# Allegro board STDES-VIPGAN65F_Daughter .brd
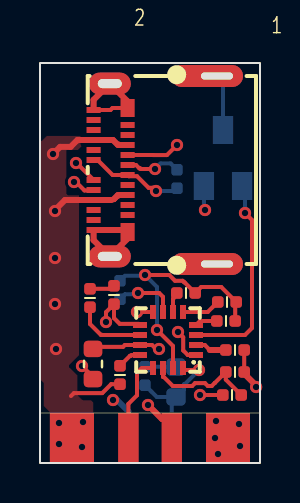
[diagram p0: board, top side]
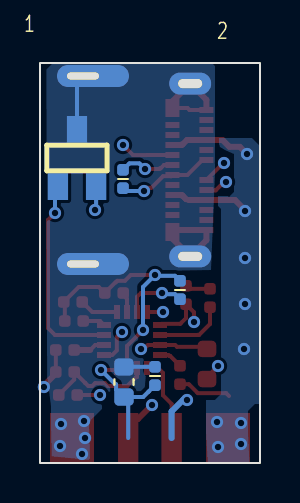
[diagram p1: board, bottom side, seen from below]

Outline 11 x 20 mm; copper layers: TOP, LAYER_1, LAYER_2, BOTTOM. Coordinates in mm from the lower left corner of the outline.
Outline path: rectangle 0,0 11,20

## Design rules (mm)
constraint set DEFAULT: 
nets with their own width: nets 2V7 GND_SIGNAL N12284642 N12284658 N12286218 N12286232 N12312816 N12312820 N12313623 N12313630 N12314144 N12315159 N12316115 N12337768 N16800338

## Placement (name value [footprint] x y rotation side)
C3  100nF  [C_0402]  5.25 4.35 90 bottom
C4  470nF  [C_0603]  6.8 4.05 90 bottom
C5  1uF  [C_0402]  4 8.65 270 bottom
C6  1uF  [C_0402]  9.75 4.55 0 top
C7  33nF  [R_0402]  3.7 8.4 270 top
D2  ESDA25L  [SOT23ST]  9.15 15.25 180 bottom
J2  USB-C-Receptacle_3  [USBCSMTMOLEX_NEW]  10.8 14.65 90 top
J5  CONN PCB 3  [PD_SBOARD]  0 2.5 0 top
NOREF  -  []  0 2.5 0 top
R5  510R  [R_0402]  4 4.4 90 top
R6  100R  [R_0402]  6.85 14.2 270 bottom
R7  0R  [R_0402]  9.75 5.65 180 top
R8  4K7  [R_0402]  9.6 3.4 180 top
R9  10K  [R_0402]  9.3 7.1 0 top
R10  4K7  [R_0402]  9.35 8.05 180 top
R11  4K7  [R_0402]  7.3 8.5 180 top
R12  3K  [R_0402]  2.5 8.25 270 top
RT1  NTC 100K  [R_0603]  2.65 4.95 270 top
U1  STUSB4761  [QFN16]  6.4 6.15 90 top

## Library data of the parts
C3-C7 = CAP NP
D2 = DIODE_DUAL_CA_JKK_2
J2 = USB-C-Receptacle_6
J5 = CONN PCB 3_1
R5-R12 = RESISTOR
RT1 = NTC
U1 = STUSB4761_0

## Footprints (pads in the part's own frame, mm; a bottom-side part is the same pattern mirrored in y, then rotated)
C_0402
  rrect 0.58x0.58 smd: 1(-0.46,0) 2(0.46,0)
C_0603
  rrect 0.87x0.97 smd: 1(-0.75,0) 2(0.75,0)
PD_SBOARD
  rect 2.2x2.5 smd: 1(1.6,-1.25) 2(1.6,-1.25) 3(9.4,-1.25) 4(9.4,-1.25)
  rect 1x2.5 smd: 5(4.42,-1.25) 6(4.42,-1.25) 7(6.59,-1.25) 8(6.59,-1.25)
QFN16
  rect 0.3x0.699 smd: 1(-0.75,-1.4) 2(-0.25,-1.4) 3(0.25,-1.4) 4(0.75,-1.4) 9(0.75,1.4) 10(0.25,1.4) 11(-0.25,1.4) 12(-0.75,1.4)
  rect 0.699x0.3 smd: 5(1.4,-0.75) 6(1.4,-0.25) 7(1.4,0.25) 8(1.4,0.75) 13(-1.4,0.75) 14(-1.4,0.25) 15(-1.4,-0.25) 16(-1.4,-0.75)
R_0402
  rrect 0.58x0.58 smd: 1(-0.46,0) 2(0.46,0)
R_0603
  rrect 0.82x0.93 smd: 1(-0.755,0) 2(0.755,0)
SOT23ST
  rect 1.016x1.4 smd: 1(-0.955,-1.4) 2(0.955,-1.4) 3(0,1.4)
USBCSMTMOLEX_NEW
  oval 1.1x2.1 hole 0.45x1.2: 25(-4.32,7.31) 26(4.32,7.31)
  oval 1.1x3.6 hole 0.35x1.6: 27(-4.7,1.95) 28(4.7,1.95)
  rect 0.3x0.699 smd: A1(-3,8.12) A2(-2.5,8.12) A3(-2,8.12) A4(-1.5,8.12) A5(-1,8.12) A6(-0.5,8.12) A7(0.5,8.12) A8(1,8.12) A9(1.5,8.12) A10(2,8.12) A11(2.5,8.12) A12(3,8.12) B2(2.25,6.42) B3(1.75,6.42) B4(1.25,6.42) B5(0.75,6.42) B6(0.25,6.42) B7(-0.25,6.42) B8(-0.75,6.42) B9(-1.25,6.42) B10(-1.75,6.42) B11(-2.25,6.42)
  rect 0.9x0.699 smd: B1(3.1,6.42) B12(-3.1,6.42)

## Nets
2V7: C5.1 R9.2 R10.1 R11.1 U1.15
GND_SIGNAL: C3.2 C4.2 C5.2 C6.2 D2.3 J2.25 J2.26 J2.27 J2.28 J2.A1 J2.A12 J2.B1 J2.B12 J5.3 J5.4 R7.1 RT1.2 U1.7
VDD: C3.1 C4.1 J5.8 U1.16
DRIVE: J5.5 U1.13
FB: C7.2 J5.6 U1.9
VOUT: J2.A4 J2.A9 J2.B4 J2.B9(VBUSB2) J5.1 J5.2 R5.1
N12284642: J2.A6 J2.B6 R6.1
N12284658: J2.A7 J2.B7 R6.2
N12286218: D2.1 J2.B5 U1.3
N12286232: D2.2 J2.A5 U1.1
N12312816: R12.2 U1.10
N12312820: C7.1 R12.1
N12313623: R11.2 U1.6
N12313630: R10.2 U1.5
N12314144: R8.2 RT1.1 U1.11
N12315159: C6.1 R8.1 U1.14
N12316115: R9.1 U1.4
N12337768: R5.2 U1.12(VSENSE)
N16800338: R7.2 U1.2
N16810216: J5.7 U1.8

Pads without a net: J2 A2 A3 A8 A10 A11 B2 B3 B8 B10 B11

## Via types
v1: diameter 0.61, hole 0.33, TOP to BOTTOM, 34 vias

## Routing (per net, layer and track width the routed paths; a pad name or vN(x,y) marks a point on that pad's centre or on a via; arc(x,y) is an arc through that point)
2V7: length 12.9
  TOP w0.2: v1(5.85,6.65) 6.65,5.85 U1.15 ; v1(5.25,9.4) 6.46,9.4 6.75,9.11 7.13,9.11 7.21,9.03 7.23,9.03 R11.1 8.06,8.8 9.06,8.8 R10.1 9.76,8 R9.2
  BOTTOM w0.2: v1(5.85,6.65) 5.85,8.8 v1(5.25,9.4) 5.21,9.36 4.25,9.36 C5.1
GND_SIGNAL: length 21.2
  TOP w0.2: J2.A12 3.52,17.65 3.62,17.75 J2.B1 ; U1.7 6.15,8.31 5.96,8.5 v1(4.9,8.5) ; 2.65,4.2 2.65,4.3 v1(2.1,4.85) ; R7.1 C6.2
  TOP w0.3: v1(10.8,3.8) 10.8,3.87 10.21,4.47 C6.2 ; J2.A12 2.68,18.16 J2.26 4.38,18.08 J2.B1 ; J2.A1 2.68,11.14 J2.25 4.38,11.22 J2.B12 4.28,11.65 J2.A1
  LAYER_1 w0.2: v1(2.1,4.85) 2.55,4.85 2.8,5.1
  BOTTOM w0.2: J2.28 9.15,19.05 D2.3 ; C5.2 4.25,8.44 4.84,8.44 v1(4.9,8.5) ; C4.2 6.79,4.81 C3.2
  vias: v1(8.8,2.1) v1(8.75,1.25) v1(8.9,0.45) v1(9.95,1.95) v1(10,0.85)
VDD: length 6.7
  TOP w0.2: v1(7.95,4.65) 7.25,4.65 U1.16
  BOTTOM w0.2: 7.2,3.9 v1(7.95,4.65) ; 7.2,3.9 7.2,3.65 6.85,3.3 C4.1 ; 7.2,3.9 7.2,3.95 ; C4.1 6.59,3.09 J5.8 ; C4.1 5.84,3.3 5.57,3.57 C3.1
DRIVE: length 4.3
  TOP w0.2: U1.13 5.09,4.75 4.85,4.51 4.85,3.39 4.42,2.96 J5.5
FB: length 9.6
  TOP w0.2: U1.9 4.95,6.96 3.99,6.96 3.7,7.24 C7.2 3.3,7.54 v1(3.3,7.05)
  LAYER_2 w0.3: v1(3.3,7.05) 3.3,4.26 3.65,3.91 v1(3.65,3.15)
  BOTTOM w0.3: v1(3.65,3.15) 3.85,3.15 4.42,2.58 J5.6
VOUT: length 11.1
  TOP w0.2: 3.58,13.15 3.72,13.15 3.96,13.39 ; R5.1 3.56,3.94 3.11,3.5 1.7,3.5 1.55,3.35
  TOP w0.3: J2.B4 3.97,15.9 3.96,15.91 3.89,15.91 3.65,16.15 J2.A9 1.87,16.15 1.53,15.81 1.01,15.81 v1(0.65,15.45) 0.63,15.43 ; 3.58,13.15 J2.A4 1.25,13.15 0.75,12.65 ; 3.69,13.19 3.89,13.39 3.96,13.39 3.97,13.4 J2.B9
  vias: v1(0.75,12.6) v1(0.75,10.25) v1(0.75,7.95) v1(0.8,5.7) v1(0.95,2) v1(0.95,0.95) v1(2.15,2.05) v1(2.1,0.8)
N12284642: length 8.6
  TOP w0.2: v1(1.8,15) 1.83,15 J2.A6 ; J2.B6 4.8,14.9 4.97,14.73 5.01,14.73 5.04,14.7 v1(5.75,14.7)
  LAYER_2 w0.2: 4.69,15 4.74,15 5.04,14.7
  LAYER_2 w0.3: v1(5.75,14.7) 4.99,14.7 4.69,15 v1(1.8,15)
  BOTTOM w0.2: R6.1 6.53,14.98 6.03,14.98 v1(5.75,14.7)
N12284658: length 4.9
  TOP w0.2: v1(5.8,13.6) 5.64,13.76 5.43,13.76 4.85,14.34 4.44,14.34 J2.B7 3.63,14.4 2.88,15.15 J2.A7
  BOTTOM w0.2: R6.2 6.71,13.6 v1(5.8,13.6)
N12286218: length 17.7
  TOP w0.2: J2.B5 5.64,15.4 5.64,15.4 6.35,15.4 v1(6.85,15.9) ; v1(10.25,12.5) 10.6,12.15 10.6,6.75 10.25,6.4 U1.3
  LAYER_2 w0.3: v1(10.25,12.5) v1(6.85,15.9)
  BOTTOM w0.2: D2.1 10.25,13.71 v1(10.25,12.5)
N12286232: length 19.4
  TOP w0.2: v1(6.9,6.55) 7.16,6.29 7.16,5.63 7.39,5.4 U1.1 ; v1(1.7,14.05) 1.8,14.05 2.22,13.63 2.66,13.63 J2.A5
  LAYER_2 w0.2: 6.83,12.43 7.05,12.65
  LAYER_2 w0.3: v1(1.7,14.05) 3.55,14.05 5.05,12.55 8.15,12.55 v1(8.25,12.65) 7.05,12.65 ; 6.83,12.43 6.15,11.75 6.15,10.2 6.05,10.1 6.05,7.4 v1(6.9,6.55)
  BOTTOM w0.2: D2.2 8.2,12.71 v1(8.25,12.65)
N12312816: length 3.6
  TOP w0.2: U1.10 3.12,6.4 3.11,6.4 3.04,6.4 2.5,6.95 R12.2
N12312820: length 1.3
  TOP w0.2: R12.1 3.45,8.71 3.6,8.86 C7.1
N12313623: length 1
  TOP w0.2: U1.6 6.65,8.21 6.69,8.25 6.69,8.35 R11.2
N12313630: length 1.9
  TOP w0.2: U1.5 8.39,7.55 8.89,8.05 R10.2
N12314144: length 8.2
  TOP w0.2: RT1.1 2.8,5.71 2.9,5.8 4.15,5.8 4.24,5.9 U1.11 5.6,5.9 5.8,5.7 v1(5.95,5.7) ; R8.2 v1(8,3.4)
  LAYER_2 w0.3: v1(8,3.4) 7.29,3.4 5.95,4.74 v1(5.95,5.7)
N12315159: length 5.7
  TOP w0.2: R8.1 9.29,4.17 C6.1 8.74,4 8.74,4 8.59,3.85 8.39,3.85 8.25,4 7.75,4 7.61,3.85 6.64,3.85 6.19,4.3 6.15,4.3 U1.14
N12316115: length 1.1
  TOP w0.2: R9.1 8,7.1 U1.4
N12337768: length 1.2
  TOP w0.2: R5.2 4.5,5.36 4.55,5.36 4.59,5.4 U1.12
N16800338: length 1.6
  TOP w0.2: 8.49,5.65 8.24,5.9 U1.2
  TOP w0.3: 8.49,5.65 R7.2
N16810216: length 8
  TOP w0.2: v1(4.85,7.55) U1.8
  TOP w0.3: v1(5.4,2.9) 6.1,2.2 6.38,2.2 6.59,1.99 J5.7
  LAYER_2 w0.3: v1(4.85,7.55) 4.85,3.45 v1(5.4,2.9)

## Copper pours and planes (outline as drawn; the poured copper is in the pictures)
GND_SIGNAL on BOTTOM: 7.9,2.95 7.9,2.7 8.55,2.05 8.5,0.15 10.41,0.34 10.45,1.8 10.45,2.85 10.64,4.34 10.68,19.67 10.4,19.95 2.35,19.95 2.25,19.85 2.25,14.5 2.45,9.65 5.3,9.6 5.8,3.25 6.15,3 6.3,2.9
GND_SIGNAL on LAYER_1: 10.43,1.86 10.96,3.27 10.89,9.2 2.8,9.3 2.25,8.85 2.2,3.85 5,3.5 8.2,2.8 8.6,1.86
GND_SIGNAL on LAYER_2: 8.55,1.55 10.35,1.5 10.36,1.37 11.12,11.24 6.75,11.35 6.75,9.3 7.7,5.8 8.6,4.9
VOUT on TOP: 0.19,4 0.19,2.85 0.48,2.56 0.48,0.04 0.46,0.02 2.6,0.02 2.66,0.07 2.66,3.02 2.55,3.13 2.14,3.13 1.87,3.4 1.87,4.38 1.48,4.77 1.45,4.77 1.45,4.89 1.95,5.39 1.95,13.36 1.92,13.39 1.38,13.39 1.32,13.45 1.32,15.63 1.34,15.65 1.89,15.65 2.28,16.04 2.28,16.35 0.33,16.35 0.07,16.09 -0.02,16.09 -0.02,4.21 0.19,4
VOUT on BOTTOM: 0.05,2.95 0.25,2.95 0.6,2.6 0.6,1.5 0.53,-0.02 2.61,-0.01 2.7,1.55 2.7,3.15 2.25,3.15 1.95,3.45 1.95,12.7 2.1,12.85 2.1,13.35 1.6,13.35 1.55,13.3 1.3,13.55 1.3,15.45 1.75,15.65 2,15.8 2.05,15.95 2.05,16.25 0.4,16.25 0.05,15.9
VOUT on LAYER_1, LAYER_2: 0.05,2.95 0.25,2.95 0.6,2.6 0.6,1.5 0.65,1.45 2.6,1.45 2.7,1.55 2.7,3.15 2.25,3.15 1.95,3.45 1.95,12.7 2.1,12.85 2.1,13.35 1.6,13.35 1.55,13.3 1.3,13.55 1.3,15.45 1.75,15.65 2,15.8 2.05,15.95 2.05,16.25 0.4,16.25 0.05,15.9

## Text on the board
Board Geometry/Soldermask Bottom: CB26.PR1
Ref Des/Silkscreen Bottom: 2 | 1 | 3 | 20210727 | ViperGaN50
Ref Des/Silkscreen Top: 2 | 1 | 3
